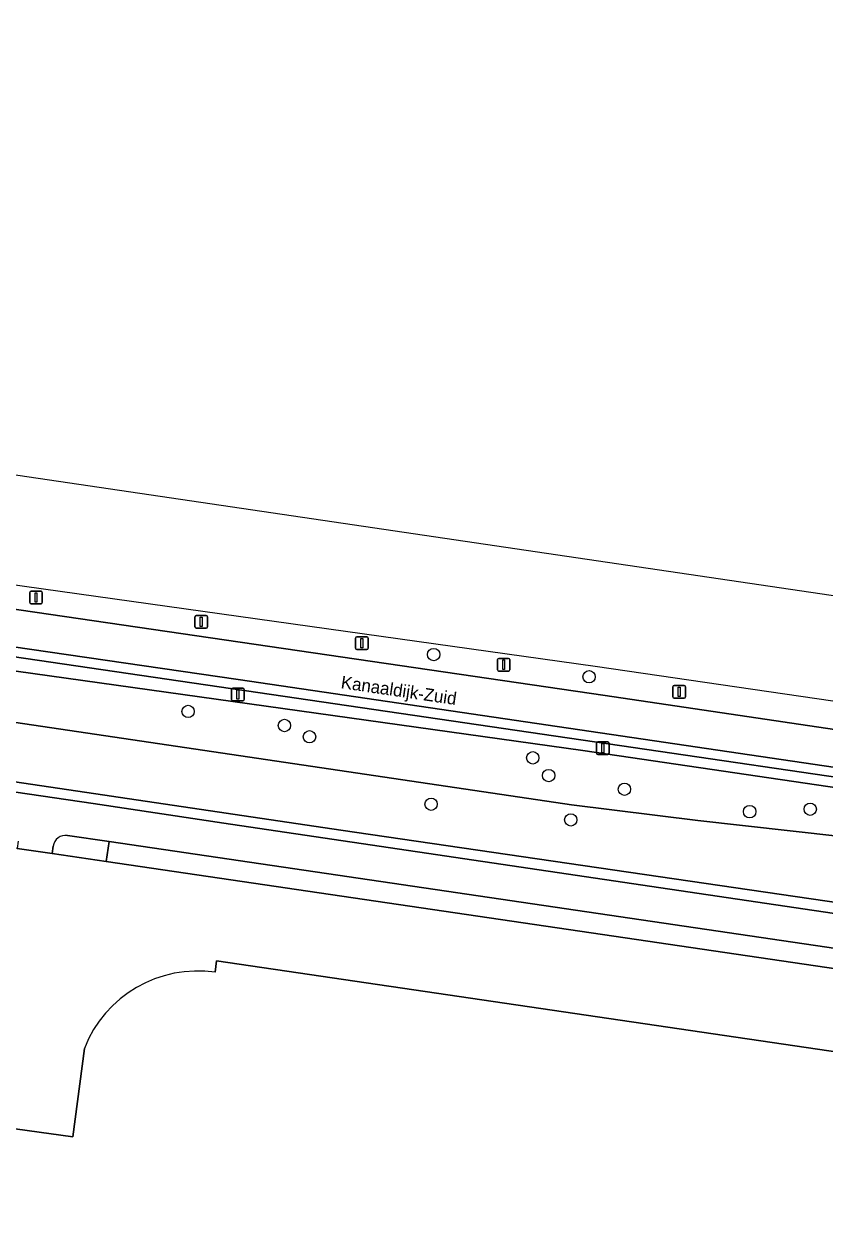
# Model space of a CAD drawing. Extents: x 163043 to 165076, y 382019 to 382874.
# Drawn here: x 163848.3 to 163911.6, y 382693.6 to 382788.6 of the extents above; entities that cross this region are included whole.
import ezdxf

# ---------------------------------------------------------------- set-up
doc = ezdxf.new("R2010")
doc.units = 0
for name, color, linetype in [('IMGEO_Afsluitpaal', 7, 'Continuous'), ('IMGEO_Berm_groen', 7, 'Continuous'), ('IMGEO_Boom', 7, 'Continuous'), ('IMGEO_Erf', 7, 'Continuous'), ('IMGEO_Fietspad_gesloten', 7, 'Continuous'), ('IMGEO_Groenvoorziening', 7, 'Continuous'), ('IMGEO_Hek', 7, 'Continuous'), ('IMGEO_Lichtmast', 7, 'Continuous'), ('IMGEO_Openbare_ruimte_label', 7, 'Continuous'), ('IMGEO_Rijbaan_lokaal_gesloten', 7, 'Continuous'), ('IMGEO_Rijbaan_lokaal_halfverhard', 7, 'Continuous'), ('IMGEO_Voetpad_open', 7, 'Continuous'), ('IMGEO_Waterloop', 7, 'Continuous')]:
    doc.layers.add(name, color=color, linetype=linetype)

msp = doc.modelspace()

# ---------------------------------------------------------------- linework, layer by layer
at = {"layer": 'IMGEO_Afsluitpaal'}
for p, q in [((163848.725, 382742.839), (163848.725, 382743.639)), ((163848.725, 382743.639), (163848.725, 382742.839)), ((163848.825, 382743.739), (163849.615, 382743.739)), ((163849.615, 382743.739), (163848.825, 382743.739)), ((163849.715, 382743.639), (163849.715, 382742.839)), ((163849.715, 382742.839), (163849.715, 382743.639)), ((163849.615, 382742.739), (163848.825, 382742.739)), ((163848.825, 382742.739), (163849.615, 382742.739)), ((163861.795, 382740.919), (163861.795, 382741.719)), ((163861.795, 382741.719), (163861.795, 382740.919)), ((163861.895, 382741.819), (163862.685, 382741.819)), ((163862.685, 382741.819), (163861.895, 382741.819)), ((163862.785, 382741.719), (163862.785, 382740.919)), ((163862.785, 382740.919), (163862.785, 382741.719)), ((163862.685, 382740.819), (163861.895, 382740.819)), ((163861.895, 382740.819), (163862.685, 382740.819)), ((163874.496, 382739.221), (163874.496, 382740.021)), ((163874.496, 382740.021), (163874.496, 382739.221)), ((163874.596, 382740.121), (163875.386, 382740.121)), ((163875.386, 382740.121), (163874.596, 382740.121)), ((163875.486, 382740.021), (163875.486, 382739.221)), ((163875.486, 382739.221), (163875.486, 382740.021)), ((163875.386, 382739.121), (163874.596, 382739.121)), ((163874.596, 382739.121), (163875.386, 382739.121)), ((163885.72, 382737.523), (163885.72, 382738.323)), ((163885.72, 382738.323), (163885.72, 382737.523)), ((163885.82, 382738.423), (163886.61, 382738.423)), ((163886.61, 382738.423), (163885.82, 382738.423)), ((163886.71, 382738.323), (163886.71, 382737.523)), ((163886.71, 382737.523), (163886.71, 382738.323)), ((163886.61, 382737.423), (163885.82, 382737.423)), ((163885.82, 382737.423), (163886.61, 382737.423)), ((163899.602, 382735.381), (163899.602, 382736.181)), ((163899.602, 382736.181), (163899.602, 382735.381)), ((163899.702, 382736.281), (163900.492, 382736.281)), ((163900.492, 382736.281), (163899.702, 382736.281)), ((163900.592, 382736.181), (163900.592, 382735.381)), ((163900.592, 382735.381), (163900.592, 382736.181)), ((163900.492, 382735.281), (163899.702, 382735.281)), ((163899.702, 382735.281), (163900.492, 382735.281))]:
    msp.add_line(p, q, dxfattribs=at)
for points in [[(163849.145, 382743.614), (163849.295, 382743.614), (163849.295, 382742.864), (163849.145, 382742.864), (163849.145, 382743.614)], [(163862.215, 382741.694), (163862.365, 382741.694), (163862.365, 382740.944), (163862.215, 382740.944), (163862.215, 382741.694)], [(163874.916, 382739.996), (163875.066, 382739.996), (163875.066, 382739.246), (163874.916, 382739.246), (163874.916, 382739.996)], [(163886.14, 382738.298), (163886.29, 382738.298), (163886.29, 382737.548), (163886.14, 382737.548), (163886.14, 382738.298)], [(163900.022, 382736.156), (163900.172, 382736.156), (163900.172, 382735.406), (163900.022, 382735.406), (163900.022, 382736.156)]]:
    msp.add_lwpolyline(points, dxfattribs=at)
for centre, start, end in [((163848.825, 382743.639), 90, 180), ((163848.825, 382743.639), 90, 180), ((163849.615, 382743.639), 0, 90), ((163849.615, 382743.639), 360, 90), ((163848.825, 382742.839), 180, 270), ((163848.825, 382742.839), 180, 270), ((163849.615, 382742.839), 270, 0), ((163849.615, 382742.839), 270, 0), ((163861.895, 382741.719), 90, 180), ((163861.895, 382741.719), 90, 180), ((163862.685, 382741.719), 0, 90), ((163862.685, 382741.719), 360, 90), ((163861.895, 382740.919), 180, 270), ((163861.895, 382740.919), 180, 270), ((163862.685, 382740.919), 270, 0), ((163862.685, 382740.919), 270, 0), ((163874.596, 382740.021), 90, 180), ((163874.596, 382740.021), 90, 180), ((163875.386, 382740.021), 0, 90), ((163875.386, 382740.021), 360, 90), ((163874.596, 382739.221), 180, 270), ((163874.596, 382739.221), 180, 270), ((163875.386, 382739.221), 270, 0), ((163875.386, 382739.221), 270, 0), ((163885.82, 382738.323), 90, 180), ((163885.82, 382738.323), 90, 180), ((163886.61, 382738.323), 0, 90), ((163886.61, 382738.323), 360, 90), ((163885.82, 382737.523), 180, 270), ((163885.82, 382737.523), 180, 270), ((163886.61, 382737.523), 270, 0), ((163886.61, 382737.523), 270, 0), ((163899.702, 382736.181), 90, 180), ((163899.702, 382736.181), 90, 180), ((163900.492, 382736.181), 0, 90), ((163900.492, 382736.181), 360, 90), ((163899.702, 382735.381), 180, 270), ((163899.702, 382735.381), 180, 270), ((163900.492, 382735.381), 270, 0), ((163900.492, 382735.381), 270, 0)]:
    msp.add_arc(centre, 0.1, start, end, dxfattribs=at)
at = {"layer": 'IMGEO_Berm_groen'}
msp.add_lwpolyline([(163855.009, 382723.921), (163854.781, 382722.338), (164000, 382700.978), (164006.839, 382699.966), (164007.059, 382701.549)], close=True, dxfattribs=at)
at = {"layer": 'IMGEO_Boom'}
for centre in [(163880.679, 382738.725), (163892.97, 382736.964), (163861.252, 382734.22), (163868.871, 382733.111), (163870.855, 382732.217), (163888.516, 382730.553), (163889.776, 382729.153), (163895.767, 382728.065), (163880.474, 382726.883), (163905.676, 382726.293), (163910.468, 382726.489), (163891.526, 382725.643)]:
    msp.add_circle(centre, 0.489, dxfattribs=at)
at = {"layer": 'IMGEO_Erf'}
for points in [[(163994.295, 382695.269), (163863.495, 382714.492), (163863.395, 382713.588)], [(163853.046, 382707.563), (163852.126, 382700.572), (163838.609, 382702.43)]]:
    msp.add_lwpolyline(points, dxfattribs=at)
msp.add_arc((163862.011, 382704.065), 9.623, 81.72918, 158.6852, dxfattribs=at)
at = {"layer": 'IMGEO_Fietspad_gesloten'}
for points in [[(163481.325, 382792.879), (163658.895, 382766.971), (163694.367, 382761.678), (163717.855, 382758.173), (163777.024, 382749.582), (163865.216, 382736.756), (163935.195, 382726.449), (163935.706, 382729.346), (163894.236, 382735.483), (163777.459, 382752.55), (163718.279, 382761.093), (163718.274, 382760.992), (163694.748, 382764.503), (163659.313, 382769.79), (163600.156, 382778.493), (163481.754, 382795.747)], [(164027.346, 382701.078), (164001.814, 382704.896), (163972.988, 382709.208), (163941.301, 382713.95), (163899.357, 382720.169), (163864.594, 382725.295), (163853.752, 382726.926), (163828.341, 382730.656), (163782.57, 382737.301), (163742.98, 382743.162), (163672.738, 382753.498), (163608.806, 382762.898), (163587.397, 382766.112), (163537.527, 382773.308), (163534.167, 382773.832)], [(163847.804, 382723.971), (163847.716, 382723.378), (163850.487, 382722.97), (163850.574, 382723.563)], [(163851.709, 382724.407), (163855.009, 382723.921), (164007.059, 382701.549), (164010.063, 382701.107)]]:
    msp.add_lwpolyline(points, dxfattribs=at)
msp.add_arc((163851.564, 382723.417), 1.001, 81.6669, 171.603, dxfattribs=at)
at = {"layer": 'IMGEO_Groenvoorziening'}
for points in [[(163901.567, 382725.599), (163891.577, 382726.842), (163814.144, 382738.31), (163792.781, 382741.613), (163745.19, 382750), (163693.632, 382755.703), (163644.405, 382763.311), (163599.031, 382769.818), (163550.484, 382777.737), (163531.314, 382780.734), (163500, 382785.306), (163403.559, 382799.387), (163402.773, 382799.535), (163335.611, 382812.21), (163322.881, 382814.496)], [(163481.754, 382795.747), (163600.156, 382778.493), (163659.313, 382769.79), (163694.748, 382764.503), (163718.274, 382760.992), (163718.279, 382761.093), (163777.459, 382752.55), (163894.236, 382735.483), (163935.706, 382729.346), (163983.801, 382722.229), (164052.707, 382712.032), (164052.689, 382711.933), (164086.535, 382706.991), (164187.425, 382691.718), (164210.531, 382688.005), (164226.499, 382685.654), (164235.353, 382684.544), (164278.139, 382678.223), (164284.348, 382677.276), (164396.302, 382660.186)], [(163893.441, 382737.78), (163842.636, 382744.898), (163808.816, 382750), (163787.83, 382753.166), (163750, 382758.526), (163695.041, 382766.675), (163550.358, 382788.129), (163500, 382795.745)], [(163942.52, 382724.63), (163797.091, 382745.94), (163724.042, 382756.554), (163665.194, 382765.268), (163586.489, 382776.803), (163535.085, 382784.385), (163477.857, 382792.736)], [(163500, 382787.559), (163548.659, 382779.976), (163558.309, 382778.65), (163599.589, 382773.465), (163691.996, 382760.32), (163694.14, 382759.995), (163759.965, 382750), (163780.573, 382747.057), (163793.379, 382745.359), (163843.661, 382737.953), (163892.468, 382731.136), (163941.474, 382723.93)], [(164518.363, 382627.934), (164282.56, 382663.334), (164217.654, 382673.071), (164197.416, 382676.273), (164103.911, 382690.521), (164080.424, 382694.019), (163981.599, 382708.675), (163943.506, 382714.374), (163916.499, 382718.52), (163873.328, 382724.839), (163846.1, 382728.875), (163828.805, 382731.358), (163693.062, 382751.358), (163550.623, 382772.334), (163535.412, 382774.595), (163500, 382779.474)], [(163500, 382779.474), (163535.412, 382774.595), (163550.623, 382772.334), (163693.062, 382751.358), (163828.805, 382731.358), (163846.1, 382728.875), (163873.328, 382724.839), (163916.499, 382718.52), (163943.506, 382714.374), (163981.599, 382708.675), (164080.424, 382694.019), (164103.911, 382690.521), (164197.416, 382676.273), (164217.654, 382673.071), (164282.56, 382663.334), (164518.363, 382627.934)], [(163534.167, 382773.832), (163537.527, 382773.308), (163587.397, 382766.112), (163608.806, 382762.898), (163672.738, 382753.498), (163742.98, 382743.162), (163782.57, 382737.301), (163828.341, 382730.656), (163853.752, 382726.926), (163864.594, 382725.295), (163899.357, 382720.169), (163941.301, 382713.95)], [(164619.098, 382628.475), (164619.495, 382628.716), (164577.644, 382634.593), (164500, 382645.865), (164326.615, 382672.419), (164284.549, 382678.701), (164223.393, 382687.834), (164004.158, 382721.056), (164000, 382721.521), (163996.616, 382722.002), (163984.14, 382724.047), (163984.256, 382724.667), (163957.081, 382728.483), (163893.441, 382737.78)], [(163960.724, 382718.961), (163901.567, 382725.599)]]:
    msp.add_lwpolyline(points, dxfattribs=at)
at = {"layer": 'IMGEO_Hek'}
msp.add_lwpolyline([(163981.599, 382708.675), (163943.506, 382714.374), (163916.499, 382718.52), (163873.328, 382724.839), (163846.1, 382728.875), (163828.805, 382731.358), (163693.062, 382751.358)], dxfattribs=at)
at = {"layer": 'IMGEO_Lichtmast'}
for p, q in [((163864.691, 382735.167), (163864.691, 382735.967)), ((163864.691, 382735.967), (163864.691, 382735.167)), ((163864.791, 382736.067), (163865.581, 382736.067)), ((163865.581, 382736.067), (163864.791, 382736.067)), ((163865.681, 382735.967), (163865.681, 382735.167)), ((163865.681, 382735.167), (163865.681, 382735.967)), ((163865.581, 382735.067), (163864.791, 382735.067)), ((163864.791, 382735.067), (163865.581, 382735.067)), ((163893.56, 382730.913), (163893.56, 382731.713)), ((163893.56, 382731.713), (163893.56, 382730.913)), ((163893.66, 382731.813), (163894.45, 382731.813)), ((163894.45, 382731.813), (163893.66, 382731.813)), ((163894.55, 382731.713), (163894.55, 382730.913)), ((163894.55, 382730.913), (163894.55, 382731.713)), ((163894.45, 382730.813), (163893.66, 382730.813)), ((163893.66, 382730.813), (163894.45, 382730.813))]:
    msp.add_line(p, q, dxfattribs=at)
for points in [[(163865.111, 382735.942), (163865.261, 382735.942), (163865.261, 382735.192), (163865.111, 382735.192), (163865.111, 382735.942)], [(163893.98, 382731.688), (163894.13, 382731.688), (163894.13, 382730.938), (163893.98, 382730.938), (163893.98, 382731.688)]]:
    msp.add_lwpolyline(points, dxfattribs=at)
for centre, start, end in [((163864.791, 382735.967), 90, 180), ((163864.791, 382735.967), 90, 180), ((163865.581, 382735.967), 0, 90), ((163865.581, 382735.967), 360, 90), ((163864.791, 382735.167), 180, 270), ((163864.791, 382735.167), 180, 270), ((163865.581, 382735.167), 270, 0), ((163865.581, 382735.167), 270, 0), ((163893.66, 382731.713), 90, 180), ((163893.66, 382731.713), 90, 180), ((163894.45, 382731.713), 0, 90), ((163894.45, 382731.713), 360, 90), ((163893.66, 382730.913), 180, 270), ((163893.66, 382730.913), 180, 270), ((163894.45, 382730.913), 270, 0), ((163894.45, 382730.913), 270, 0)]:
    msp.add_arc(centre, 0.1, start, end, dxfattribs=at)
at = {"layer": 'IMGEO_Rijbaan_lokaal_gesloten'}
for points in [[(164000, 382700.978), (163854.781, 382722.338), (163850.487, 382722.97), (163847.716, 382723.378), (163843.598, 382723.984), (163831.843, 382725.713), (163666.717, 382750), (163556.902, 382766.152), (163552.586, 382766.787), (163550.541, 382767.088), (163546.296, 382767.712), (163537.821, 382768.959), (163533.739, 382769.559), (163530.738, 382770.001), (163526.731, 382770.59), (163500, 382774.522)], [(163863.395, 382713.588), (163863.495, 382714.492), (163994.295, 382695.269)], [(163838.609, 382702.43), (163852.126, 382700.572), (163853.046, 382707.563)]]:
    msp.add_lwpolyline(points, dxfattribs=at)
msp.add_arc((163862.011, 382704.065), 9.623, 81.72918, 158.6852, dxfattribs=at)
at = {"layer": 'IMGEO_Rijbaan_lokaal_halfverhard'}
for points in [[(163477.857, 382792.736), (163535.085, 382784.385), (163586.489, 382776.803), (163665.194, 382765.268), (163724.042, 382756.554), (163797.091, 382745.94), (163942.52, 382724.63), (163982.946, 382718.817), (164038.676, 382710.503), (164106.209, 382700.449), (164167.934, 382691.092), (164227.926, 382681.903), (164243.958, 382679.585), (164325.735, 382667.171), (164396.201, 382656.226)], [(164583.756, 382629.042), (164578.551, 382629.906), (164564.09, 382632.104), (164542.708, 382635.315), (164513.64, 382639.781), (164454.541, 382648.561), (164395.881, 382657.418), (164283.956, 382674.503), (164277.721, 382675.455), (164234.944, 382681.774), (164226.112, 382682.881), (164210.098, 382685.238), (164199.47, 382687.051), (164086.122, 382704.221), (163983.267, 382719.369), (163935.195, 382726.449), (163865.216, 382736.756), (163777.024, 382749.582)]]:
    msp.add_lwpolyline(points, dxfattribs=at)
at = {"layer": 'IMGEO_Voetpad_open'}
for points in [[(163850.574, 382723.563), (163850.487, 382722.97), (163854.781, 382722.338), (163855.009, 382723.921)], [(163855.009, 382723.921), (163851.709, 382724.407)]]:
    msp.add_lwpolyline(points, dxfattribs=at)
msp.add_arc((163851.564, 382723.417), 1.001, 81.6669, 171.603, dxfattribs=at)
at = {"layer": 'IMGEO_Waterloop'}
for points in [[(163123.715, 382866.341), (163125.436, 382874.202), (163542.415, 382797.919), (163683.113, 382777.184), (164147.904, 382708.691), (165075.563, 382573.631)], [(163961.285, 382721.227), (163941.474, 382723.93), (163892.468, 382731.136), (163843.661, 382737.953), (163793.379, 382745.359), (163780.573, 382747.057), (163759.965, 382750), (163694.14, 382759.995), (163691.996, 382760.32), (163599.589, 382773.465), (163558.309, 382778.65), (163548.659, 382779.976), (163500, 382787.559), (163422.96, 382799.566), (163403.342, 382803.034), (163359.301, 382810.82), (163337.612, 382814.835), (163323.297, 382816.839)], [(163322.881, 382814.496), (163335.611, 382812.21), (163402.773, 382799.535), (163403.559, 382799.387), (163500, 382785.306), (163531.314, 382780.734), (163550.484, 382777.737), (163599.031, 382769.818), (163644.405, 382763.311), (163693.632, 382755.703), (163745.19, 382750), (163792.781, 382741.613), (163814.144, 382738.31), (163891.577, 382726.842), (163901.567, 382725.599), (163960.724, 382718.961)], [(164390.464, 382663.821), (164301.167, 382677.11), (164284.681, 382679.592), (164000, 382722.456), (163984.256, 382724.667), (163957.081, 382728.483), (163893.441, 382737.78), (163842.636, 382744.898), (163808.816, 382750), (163787.83, 382753.166), (163750, 382758.526), (163695.041, 382766.675), (163550.358, 382788.129), (163500, 382795.745)]]:
    msp.add_lwpolyline(points, dxfattribs=at)

# ---------------------------------------------------------------- texts
at = {"layer": 'IMGEO_Openbare_ruimte_label'}
msp.add_text('Kanaaldijk-Zuid', height=1, rotation=351.65913, dxfattribs=at).set_placement((163873.292, 382736.067))

doc.saveas('drawing.dxf')
